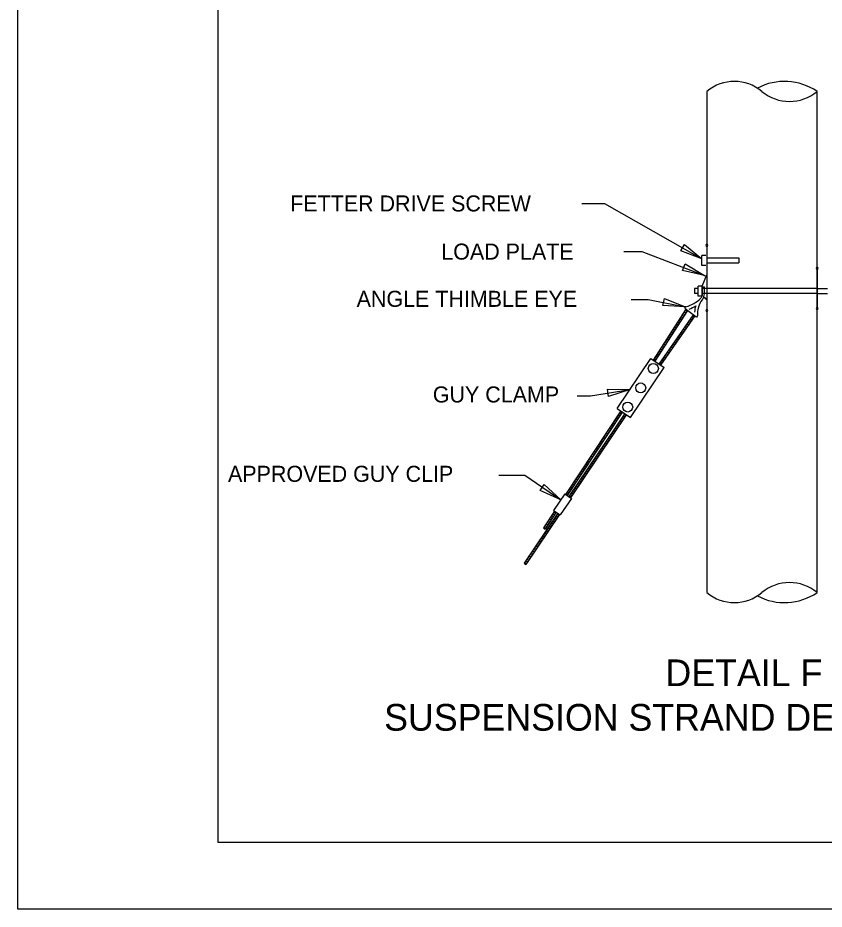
# Model space of a CAD drawing. Extents: x 1299104.8 to 1299141.6, y 239639.8 to 239661.8.
# Drawn here: x 1299104.8 to 1299110.83, y 239639.79 to 239646.46 of the extents above; entities that cross this region are included whole.
import ezdxf

# ---------------------------------------------------------------- set-up
doc = ezdxf.new("R2010")
doc.units = 0
for name, color, linetype in [('DIM TXT', 7, 'Continuous'), ('GS_plotshape_p', 7, 'Continuous'), ('Level 1', 7, 'Continuous')]:
    doc.layers.add(name, color=color, linetype=linetype)

msp = doc.modelspace()

# ---------------------------------------------------------------- linework, layer by layer
at = {"layer": 'DIM TXT'}
for p, q in [((1299109.9567, 239645.91), (1299109.9567, 239642.16)), ((1299110.7817, 239642.16), (1299110.7817, 239645.91)), ((1299109.0209, 239645.0721), (1299109.1906, 239645.0721)), ((1299109.1906, 239645.0721), (1299109.9192, 239644.657)), ((1299109.3371, 239644.7128), (1299109.4707, 239644.7128)), ((1299109.4707, 239644.7128), (1299109.9532, 239644.5282)), ((1299109.9192, 239644.6084), (1299109.9192, 239644.6834)), ((1299109.9492, 239644.6834), (1299109.9192, 239644.6834)), ((1299109.9492, 239644.6084), (1299109.9192, 239644.6084)), ((1299109.9567, 239644.6647), (1299110.1967, 239644.6647)), ((1299109.9567, 239644.6272), (1299110.1967, 239644.6272)), ((1299110.1967, 239644.6647), (1299110.1967, 239644.6272)), ((1299109.9212, 239644.4537), (1299109.9567, 239644.5365)), ((1299109.8912, 239644.4362), (1299109.8639, 239644.4362)), ((1299109.8639, 239644.4362), (1299109.8639, 239644.3987)), ((1299109.9212, 239644.4537), (1299109.8912, 239644.4537)), ((1299109.8912, 239644.3787), (1299109.8912, 239644.4537)), ((1299109.9212, 239644.3787), (1299109.9212, 239644.4537)), ((1299110.7817, 239644.4362), (1299109.9212, 239644.4362)), ((1299109.9255, 239644.4477), (1299109.9391, 239644.4477)), ((1299109.9255, 239644.3972), (1299109.9255, 239644.4477)), ((1299109.9391, 239644.3964), (1299109.9391, 239644.4477)), ((1299110.7817, 239644.4362), (1299110.8591, 239644.4362)), ((1299109.3911, 239644.3535), (1299109.517, 239644.3535)), ((1299109.517, 239644.3535), (1299109.7957, 239644.2975)), ((1299109.8912, 239644.3987), (1299109.8639, 239644.3987)), ((1299109.9212, 239644.3787), (1299109.8912, 239644.3787)), ((1299110.7817, 239644.3987), (1299109.9212, 239644.3987)), ((1299109.9338, 239644.3698), (1299109.9567, 239644.3537)), ((1299110.7817, 239644.3987), (1299110.8591, 239644.3987)), ((1299109.5569, 239643.899), (1299109.8031, 239644.28)), ((1299109.7957, 239644.2856), (1299109.8759, 239644.2247)), ((1299109.5694, 239643.8907), (1299109.8151, 239644.2709)), ((1299109.5997, 239643.8703), (1299109.8568, 239644.2393)), ((1299109.6121, 239643.862), (1299109.8686, 239644.23)), ((1299109.7734, 239644.2064), (1299109.7526, 239644.2019)), ((1299109.7815, 239644.219), (1299109.7608, 239644.2145)), ((1299109.7897, 239644.2316), (1299109.7689, 239644.2271)), ((1299109.7978, 239644.2442), (1299109.7771, 239644.2397)), ((1299109.8059, 239644.2568), (1299109.7852, 239644.2523)), ((1299109.8141, 239644.2694), (1299109.7933, 239644.2649)), ((1299109.8585, 239644.2155), (1299109.8377, 239644.2118)), ((1299109.8671, 239644.2278), (1299109.8462, 239644.2241)), ((1299109.7327, 239644.1434), (1299109.7119, 239644.1389)), ((1299109.7408, 239644.156), (1299109.7201, 239644.1515)), ((1299109.7489, 239644.1686), (1299109.7282, 239644.1641)), ((1299109.7571, 239644.1812), (1299109.7363, 239644.1767)), ((1299109.7652, 239644.1938), (1299109.7445, 239644.1893)), ((1299109.8071, 239644.1417), (1299109.7862, 239644.138)), ((1299109.8157, 239644.154), (1299109.7948, 239644.1503)), ((1299109.8242, 239644.1663), (1299109.8034, 239644.1626)), ((1299109.8328, 239644.1786), (1299109.8119, 239644.1749)), ((1299109.8414, 239644.1909), (1299109.8205, 239644.1872)), ((1299109.85, 239644.2032), (1299109.8291, 239644.1995)), ((1299109.692, 239644.0804), (1299109.6712, 239644.0759)), ((1299109.7001, 239644.093), (1299109.6794, 239644.0885)), ((1299109.7082, 239644.1056), (1299109.6875, 239644.1011)), ((1299109.7164, 239644.1182), (1299109.6956, 239644.1137)), ((1299109.7245, 239644.1308), (1299109.7038, 239644.1263)), ((1299109.7642, 239644.0802), (1299109.7433, 239644.0764)), ((1299109.7728, 239644.0925), (1299109.7519, 239644.0887)), ((1299109.7814, 239644.1048), (1299109.7605, 239644.101)), ((1299109.7899, 239644.1171), (1299109.7691, 239644.1134)), ((1299109.7985, 239644.1294), (1299109.7776, 239644.1257)), ((1299109.6431, 239644.0048), (1299109.6224, 239644.0004)), ((1299109.6513, 239644.0174), (1299109.6305, 239644.013)), ((1299109.6594, 239644.03), (1299109.6387, 239644.0256)), ((1299109.6675, 239644.0426), (1299109.6468, 239644.0382)), ((1299109.6757, 239644.0552), (1299109.6549, 239644.0508)), ((1299109.6838, 239644.0678), (1299109.6631, 239644.0633)), ((1299109.7128, 239644.0063), (1299109.6919, 239644.0026)), ((1299109.7213, 239644.0186), (1299109.7004, 239644.0149)), ((1299109.7299, 239644.0309), (1299109.709, 239644.0272)), ((1299109.7385, 239644.0432), (1299109.7176, 239644.0395)), ((1299109.7471, 239644.0556), (1299109.7262, 239644.0518)), ((1299109.7556, 239644.0679), (1299109.7347, 239644.0641)), ((1299109.6024, 239643.9418), (1299109.5817, 239643.9374)), ((1299109.6105, 239643.9544), (1299109.5898, 239643.95)), ((1299109.6187, 239643.967), (1299109.5979, 239643.9626)), ((1299109.6268, 239643.9796), (1299109.6061, 239643.9752)), ((1299109.635, 239643.9922), (1299109.6142, 239643.9878)), ((1299109.6699, 239643.9448), (1299109.649, 239643.9411)), ((1299109.6784, 239643.9571), (1299109.6576, 239643.9534)), ((1299109.687, 239643.9694), (1299109.6661, 239643.9657)), ((1299109.6956, 239643.9817), (1299109.6747, 239643.978)), ((1299109.7042, 239643.994), (1299109.6833, 239643.9903)), ((1299109.2872, 239643.5381), (1299109.538, 239643.9118)), ((1299109.538, 239643.9118), (1299109.6376, 239643.8449)), ((1299109.578, 239643.904), (1299109.5572, 239643.8996)), ((1299109.5861, 239643.9166), (1299109.5654, 239643.9122)), ((1299109.5698, 239643.8914), (1299109.5688, 239643.8912)), ((1299109.5943, 239643.9292), (1299109.5735, 239643.9248)), ((1299109.627, 239643.8833), (1299109.6061, 239643.8795)), ((1299109.6356, 239643.8956), (1299109.6147, 239643.8918)), ((1299109.6441, 239643.9079), (1299109.6233, 239643.9041)), ((1299109.6527, 239643.9202), (1299109.6318, 239643.9165)), ((1299109.6613, 239643.9325), (1299109.6404, 239643.9288)), ((1299109.3868, 239643.4713), (1299109.6376, 239643.8449)), ((1299109.6184, 239643.871), (1299109.6031, 239643.8682)), ((1299109.0878, 239643.6331), (1299109.3829, 239643.6807)), ((1299108.9875, 239643.6331), (1299109.0878, 239643.6331)), ((1299109.2872, 239643.5381), (1299109.3868, 239643.4713)), ((1299109.3126, 239643.521), (1299108.9003, 239642.8945)), ((1299109.3252, 239643.5128), (1299108.9128, 239642.8862)), ((1299109.3424, 239643.5011), (1299108.9252, 239642.8778)), ((1299109.3548, 239643.4927), (1299108.9377, 239642.8694)), ((1299109.2809, 239643.4728), (1299109.3015, 239643.4768)), ((1299109.289, 239643.4851), (1299109.3096, 239643.4891)), ((1299109.2971, 239643.4974), (1299109.3177, 239643.5015)), ((1299109.3052, 239643.5097), (1299109.3258, 239643.5138)), ((1299109.3251, 239643.4753), (1299109.3459, 239643.4794)), ((1299109.3335, 239643.4878), (1299109.3543, 239643.4919)), ((1299109.2404, 239643.4113), (1299109.261, 239643.4153)), ((1299109.2485, 239643.4236), (1299109.2691, 239643.4276)), ((1299109.2566, 239643.4359), (1299109.2772, 239643.4399)), ((1299109.2647, 239643.4482), (1299109.2853, 239643.4522)), ((1299109.2728, 239643.4605), (1299109.2934, 239643.4645)), ((1299109.2752, 239643.4006), (1299109.2959, 239643.4047)), ((1299109.2835, 239643.4131), (1299109.3043, 239643.4172)), ((1299109.2918, 239643.4255), (1299109.3126, 239643.4296)), ((1299109.3002, 239643.438), (1299109.3209, 239643.4421)), ((1299109.3085, 239643.4504), (1299109.3293, 239643.4545)), ((1299109.3168, 239643.4629), (1299109.3376, 239643.467)), ((1299109.1918, 239643.3374), (1299109.2124, 239643.3415)), ((1299109.1999, 239643.3497), (1299109.2205, 239643.3538)), ((1299109.208, 239643.3621), (1299109.2286, 239643.3661)), ((1299109.2161, 239643.3744), (1299109.2367, 239643.3784)), ((1299109.2242, 239643.3867), (1299109.2448, 239643.3907)), ((1299109.2323, 239643.399), (1299109.2529, 239643.403)), ((1299109.2335, 239643.3384), (1299109.2543, 239643.3425)), ((1299109.2418, 239643.3509), (1299109.2626, 239643.3549)), ((1299109.2502, 239643.3633), (1299109.2709, 239643.3674)), ((1299109.2585, 239643.3757), (1299109.2793, 239643.3798)), ((1299109.2668, 239643.3882), (1299109.2876, 239643.3923)), ((1299109.1513, 239643.2759), (1299109.1719, 239643.28)), ((1299109.1594, 239643.2882), (1299109.18, 239643.2923)), ((1299109.1675, 239643.3005), (1299109.1881, 239643.3046)), ((1299109.1756, 239643.3128), (1299109.1962, 239643.3169)), ((1299109.1837, 239643.3251), (1299109.2043, 239643.3292)), ((1299109.1918, 239643.2762), (1299109.2126, 239643.2802)), ((1299109.2002, 239643.2886), (1299109.221, 239643.2927)), ((1299109.2085, 239643.3011), (1299109.2293, 239643.3051)), ((1299109.2168, 239643.3135), (1299109.2376, 239643.3176)), ((1299109.2252, 239643.326), (1299109.246, 239643.33)), ((1299109.1027, 239643.2021), (1299109.1234, 239643.2062)), ((1299109.1108, 239643.2144), (1299109.1315, 239643.2185)), ((1299109.1189, 239643.2267), (1299109.1396, 239643.2308)), ((1299109.127, 239643.239), (1299109.1476, 239643.2431)), ((1299109.1351, 239643.2513), (1299109.1557, 239643.2554)), ((1299109.1418, 239643.2015), (1299109.1626, 239643.2056)), ((1299109.1432, 239643.2636), (1299109.1638, 239643.2677)), ((1299109.1502, 239643.2139), (1299109.171, 239643.218)), ((1299109.1585, 239643.2264), (1299109.1793, 239643.2305)), ((1299109.1668, 239643.2388), (1299109.1876, 239643.2429)), ((1299109.1752, 239643.2513), (1299109.196, 239643.2553)), ((1299109.1835, 239643.2637), (1299109.2043, 239643.2678)), ((1299109.0622, 239643.1406), (1299109.0829, 239643.1446)), ((1299109.0703, 239643.1529), (1299109.091, 239643.1569)), ((1299109.0784, 239643.1652), (1299109.0991, 239643.1693)), ((1299109.0865, 239643.1775), (1299109.1072, 239643.1816)), ((1299109.0946, 239643.1898), (1299109.1153, 239643.1939)), ((1299109.1002, 239643.1392), (1299109.121, 239643.1433)), ((1299109.1085, 239643.1517), (1299109.1293, 239643.1558)), ((1299109.1168, 239643.1641), (1299109.1376, 239643.1682)), ((1299109.1252, 239643.1766), (1299109.146, 239643.1807)), ((1299109.1335, 239643.189), (1299109.1543, 239643.1931)), ((1299109.0218, 239643.0791), (1299109.0424, 239643.0831)), ((1299109.0299, 239643.0914), (1299109.0505, 239643.0954)), ((1299109.038, 239643.1037), (1299109.0586, 239643.1077)), ((1299109.0461, 239643.116), (1299109.0667, 239643.12)), ((1299109.0541, 239643.1283), (1299109.0748, 239643.1323)), ((1299109.0585, 239643.077), (1299109.0793, 239643.0811)), ((1299109.0669, 239643.0894), (1299109.0876, 239643.0935)), ((1299109.0752, 239643.1019), (1299109.096, 239643.106)), ((1299109.0835, 239643.1143), (1299109.1043, 239643.1184)), ((1299109.0919, 239643.1268), (1299109.1126, 239643.1309)), ((1299108.4015, 239643.0374), (1299108.5942, 239643.0374)), ((1299108.5942, 239643.0374), (1299108.8634, 239642.853)), ((1299108.9732, 239643.0052), (1299108.9938, 239643.0093)), ((1299108.9813, 239643.0176), (1299109.0019, 239643.0216)), ((1299108.9894, 239643.0299), (1299109.01, 239643.0339)), ((1299108.9975, 239643.0422), (1299109.0181, 239643.0462)), ((1299109.0056, 239643.0545), (1299109.0262, 239643.0585)), ((1299109.0085, 239643.0023), (1299109.0293, 239643.0064)), ((1299109.0137, 239643.0668), (1299109.0343, 239643.0708)), ((1299109.0169, 239643.0147), (1299109.0377, 239643.0188)), ((1299109.0252, 239643.0272), (1299109.046, 239643.0313)), ((1299109.0335, 239643.0396), (1299109.0543, 239643.0437)), ((1299109.0419, 239643.0521), (1299109.0626, 239643.0562)), ((1299109.0502, 239643.0645), (1299109.071, 239643.0686)), ((1299108.9327, 239642.9437), (1299108.9533, 239642.9478)), ((1299108.9408, 239642.956), (1299108.9614, 239642.9601)), ((1299108.9489, 239642.9683), (1299108.9695, 239642.9724)), ((1299108.957, 239642.9806), (1299108.9776, 239642.9847)), ((1299108.9651, 239642.9929), (1299108.9857, 239642.997)), ((1299108.9669, 239642.94), (1299108.9877, 239642.9441)), ((1299108.9752, 239642.9525), (1299108.996, 239642.9566)), ((1299108.9835, 239642.9649), (1299109.0043, 239642.969)), ((1299108.9919, 239642.9774), (1299109.0127, 239642.9815)), ((1299109.0002, 239642.9898), (1299109.021, 239642.9939)), ((1299108.8941, 239642.8987), (1299108.8105, 239642.7742)), ((1299108.8941, 239642.8987), (1299108.9439, 239642.8653)), ((1299108.9003, 239642.8945), (1299108.9209, 239642.8986)), ((1299108.9084, 239642.9068), (1299108.929, 239642.9109)), ((1299108.9165, 239642.9191), (1299108.9371, 239642.9232)), ((1299108.9246, 239642.9314), (1299108.9452, 239642.9355)), ((1299108.9252, 239642.8778), (1299108.946, 239642.8819)), ((1299108.9335, 239642.8902), (1299108.9543, 239642.8943)), ((1299108.9419, 239642.9027), (1299108.9627, 239642.9068)), ((1299108.9502, 239642.9151), (1299108.971, 239642.9192)), ((1299108.9585, 239642.9276), (1299108.9793, 239642.9317)), ((1299108.9439, 239642.8653), (1299108.8603, 239642.7407)), ((1299108.8418, 239642.7531), (1299108.5915, 239642.3792)), ((1299108.8542, 239642.7448), (1299108.6039, 239642.3708)), ((1299108.8178, 239642.7692), (1299108.7354, 239642.6439)), ((1299108.8303, 239642.7608), (1299108.7478, 239642.6355)), ((1299108.8008, 239642.7432), (1299108.8214, 239642.7473)), ((1299108.8089, 239642.7557), (1299108.8296, 239642.7597)), ((1299108.8105, 239642.7742), (1299108.8603, 239642.7407)), ((1299108.8331, 239642.7402), (1299108.8539, 239642.7443)), ((1299108.7517, 239642.6687), (1299108.7723, 239642.6728)), ((1299108.7599, 239642.6812), (1299108.7805, 239642.6852)), ((1299108.7681, 239642.6936), (1299108.7887, 239642.6976)), ((1299108.7762, 239642.706), (1299108.7969, 239642.7101)), ((1299108.7844, 239642.7184), (1299108.805, 239642.7225)), ((1299108.7915, 239642.6779), (1299108.8122, 239642.682)), ((1299108.7926, 239642.7308), (1299108.8132, 239642.7349)), ((1299108.7998, 239642.6904), (1299108.8206, 239642.6945)), ((1299108.8081, 239642.7028), (1299108.8289, 239642.7069)), ((1299108.8164, 239642.7153), (1299108.8372, 239642.7194)), ((1299108.8248, 239642.7277), (1299108.8456, 239642.7318)), ((1299108.7354, 239642.6439), (1299108.756, 239642.648)), ((1299108.7354, 239642.6439), (1299108.7478, 239642.6355)), ((1299108.7415, 239642.6033), (1299108.7622, 239642.6073)), ((1299108.7435, 239642.6563), (1299108.7642, 239642.6604)), ((1299108.7498, 239642.6157), (1299108.7706, 239642.6198)), ((1299108.7581, 239642.6281), (1299108.7789, 239642.6322)), ((1299108.7665, 239642.6406), (1299108.7872, 239642.6447)), ((1299108.7748, 239642.653), (1299108.7956, 239642.6571)), ((1299108.7831, 239642.6655), (1299108.8039, 239642.6696)), ((1299108.6998, 239642.541), (1299108.7206, 239642.5451)), ((1299108.7081, 239642.5535), (1299108.7289, 239642.5575)), ((1299108.7165, 239642.5659), (1299108.7372, 239642.57)), ((1299108.7248, 239642.5784), (1299108.7456, 239642.5824)), ((1299108.7331, 239642.5908), (1299108.7539, 239642.5949)), ((1299108.6581, 239642.4788), (1299108.6789, 239642.4829)), ((1299108.6665, 239642.4912), (1299108.6873, 239642.4953)), ((1299108.6748, 239642.5037), (1299108.6956, 239642.5078)), ((1299108.6831, 239642.5161), (1299108.7039, 239642.5202)), ((1299108.6915, 239642.5286), (1299108.7123, 239642.5326)), ((1299108.6081, 239642.4041), (1299108.6289, 239642.4082)), ((1299108.6165, 239642.4165), (1299108.6373, 239642.4206)), ((1299108.6248, 239642.429), (1299108.6456, 239642.4331)), ((1299108.6331, 239642.4414), (1299108.6539, 239642.4455)), ((1299108.6415, 239642.4539), (1299108.6623, 239642.458)), ((1299108.6498, 239642.4663), (1299108.6706, 239642.4704)), ((1299108.5915, 239642.3792), (1299108.6123, 239642.3833)), ((1299108.5915, 239642.3792), (1299108.6123, 239642.3833)), ((1299108.5915, 239642.3792), (1299108.6039, 239642.3708)), ((1299108.5998, 239642.3916), (1299108.6206, 239642.3957))]:
    msp.add_line(p, q, dxfattribs=at)
for points in [[(1299109.7616, 239644.7179), (1299109.7891, 239644.7648), (1299109.9192, 239644.657)], [(1299109.7753, 239644.57), (1299109.7956, 239644.6204), (1299109.9403, 239644.5331)], [(1299109.627, 239644.3081), (1299109.6391, 239644.3611), (1299109.7957, 239644.2975)], [(1299109.2225, 239643.6274), (1299109.2138, 239643.6811), (1299109.3829, 239643.6807)], [(1299108.7102, 239642.9245), (1299108.7408, 239642.9694), (1299108.8634, 239642.853)]]:
    msp.add_lwpolyline(points, close=True, dxfattribs=at)
for points in [[(1299109.9567, 239644.7584), (1299109.9567, 239644.2709)], [(1299110.7817, 239644.5862), (1299110.7817, 239644.2862)], [(1299109.9212, 239644.4537), (1299109.9567, 239644.5365)], [(1299109.9567, 239644.3537), (1299109.9338, 239644.3698)], [(1299109.9338, 239644.3698), (1299109.9338, 239644.3698), (1299109.9338, 239644.3698), (1299109.9338, 239644.3698), (1299109.9338, 239644.3698)]]:
    msp.add_lwpolyline(points, dxfattribs=at)
for centre in [(1299109.5567, 239643.8368), (1299109.4623, 239643.6915), (1299109.3648, 239643.5486)]:
    msp.add_circle(centre, 0.0375, dxfattribs=at)
for centre, radius, start, end in [((1299110.163, 239645.6639), 0.3211, 50.03379, 129.96621), ((1299110.538, 239645.5514), 0.4336, 55.79454, 117.85169), ((1299110.5755, 239646.1561), 0.3211, 230.03379, 309.96621), ((1299109.9567, 239644.7584), 0.0075, 0, 180), ((1299109.9567, 239644.7584), 0.0075, 180, 0), ((1299110.7817, 239644.5862), 0.0075, 0, 180), ((1299110.7817, 239644.5862), 0.0075, 180, 0), ((1299109.7269, 239644.5562), 0.2675, 286.02642, 313.58773), ((1299110.0637, 239644.2468), 0.1766, 143.76489, 184.84148), ((1299109.8915, 239644.3849), 0.03, 311.57137, 334.86882), ((1299109.8944, 239644.389), 0.0295, 325.18074, 348.4872), ((1299109.8915, 239644.3849), 0.045, 311.57137, 348.91039), ((1299109.8513, 239644.4014), 0.0742, 343.38012, 356.77642), ((1299109.8513, 239644.4014), 0.0879, 343.38012, 356.77642), ((1299109.8003, 239644.2916), 0.0075, 86.0943, 232.73967), ((1299109.7269, 239644.5562), 0.2911, 289.5501, 300.33215), ((1299110.0637, 239644.2468), 0.1985, 162.98374, 176.5336), ((1299109.9567, 239644.2709), 0.0075, 0, 180), ((1299110.7817, 239644.2862), 0.0075, 0, 180), ((1299110.7817, 239644.2862), 0.0075, 180, 0), ((1299109.8804, 239644.2306), 0.0075, 232.73967, 9.96119), ((1299109.9567, 239644.2709), 0.0075, 180, 0), ((1299110.5755, 239641.914), 0.3211, 50.03379, 129.96621), ((1299110.163, 239642.4061), 0.3211, 230.03379, 309.96621), ((1299110.538, 239642.5186), 0.4336, 242.14831, 304.20546)]:
    msp.add_arc(centre, radius, start, end, dxfattribs=at)
at = {"layer": 'GS_plotshape_p'}
msp.add_lwpolyline([(1299104.8019, 239661.7913), (1299138.8019, 239661.7913), (1299138.8019, 239639.7913), (1299104.8019, 239639.7913)], close=True, dxfattribs=at)
at = {"layer": 'Level 1'}
msp.add_lwpolyline([(1299138.3019, 239640.2913), (1299106.3019, 239640.2913), (1299106.3019, 239661.2913), (1299138.3019, 239661.2913)], close=True, dxfattribs=at)

# ---------------------------------------------------------------- texts
at = {"layer": 'DIM TXT'}
for s, height, p in [('FETTER DRIVE SCREW', 0.12, (1299106.8399, 239645.0117)), ('LOAD PLATE', 0.12, (1299107.9705, 239644.6515)), ('ANGLE THIMBLE EYE', 0.12, (1299107.3369, 239644.2981)), ('GUY CLAMP', 0.12, (1299107.9069, 239643.5824)), ('APPROVED GUY CLIP', 0.12, (1299106.3745, 239642.9887)), ('DETAIL F', 0.2, (1299109.6474, 239641.46)), ('SUSPENSION STRAND DEAD-ENDING', 0.2, (1299107.5427, 239641.1267))]:
    msp.add_text(s, height=height, dxfattribs=at).set_placement(p)

doc.saveas('drawing.dxf')
